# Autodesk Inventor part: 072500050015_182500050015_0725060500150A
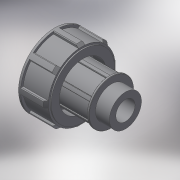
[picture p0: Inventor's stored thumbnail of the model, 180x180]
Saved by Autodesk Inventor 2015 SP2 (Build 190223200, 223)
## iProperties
Created: 2017-04
Part Number: 072500050015_182500050015_0725060500150A
Material: Generic
Description: PLASSON THREADED ADAPTOR 50-1.1/2"
Document SubType Name: Modeling
Designer: KIM
Density: 1 g/cm^3
Appearance: Default
Author: KIM
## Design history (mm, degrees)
derived "07250.ipt"
feature "Solid1::07250.ipt"
tag "TaggingFeature1"
body "Solid1"
other parameters: "d1" = 47.803, "d2" = 104, "d3" = 24, "d6" = 96, "d7" = 89.28, "d8" = 76.8, "d10" = 57.3636, "d12" = 28.6818, "d13" = 38.2424, "d14" = 27.6, "d15" = 72, "d16" = 3.12, "d17" = 41.6, "d18" = 24, "d19" = 28.8, "d24" = 9.5606, "d25" = 4.7803, "d27" = 0, "d28" = 3.82424, "d31" = 0.95606, "d35" = 360 deg, "d41" = 29.337, "d56" = 55, "d57" = 5, "d58" = 2.5, "d60" = 0, "d61" = 0.47803, "d64" = 0.47803, "d68" = 360 deg, "R_" = 47.803, "E_" = 96, "H_" = 104, "l_2" = 24
